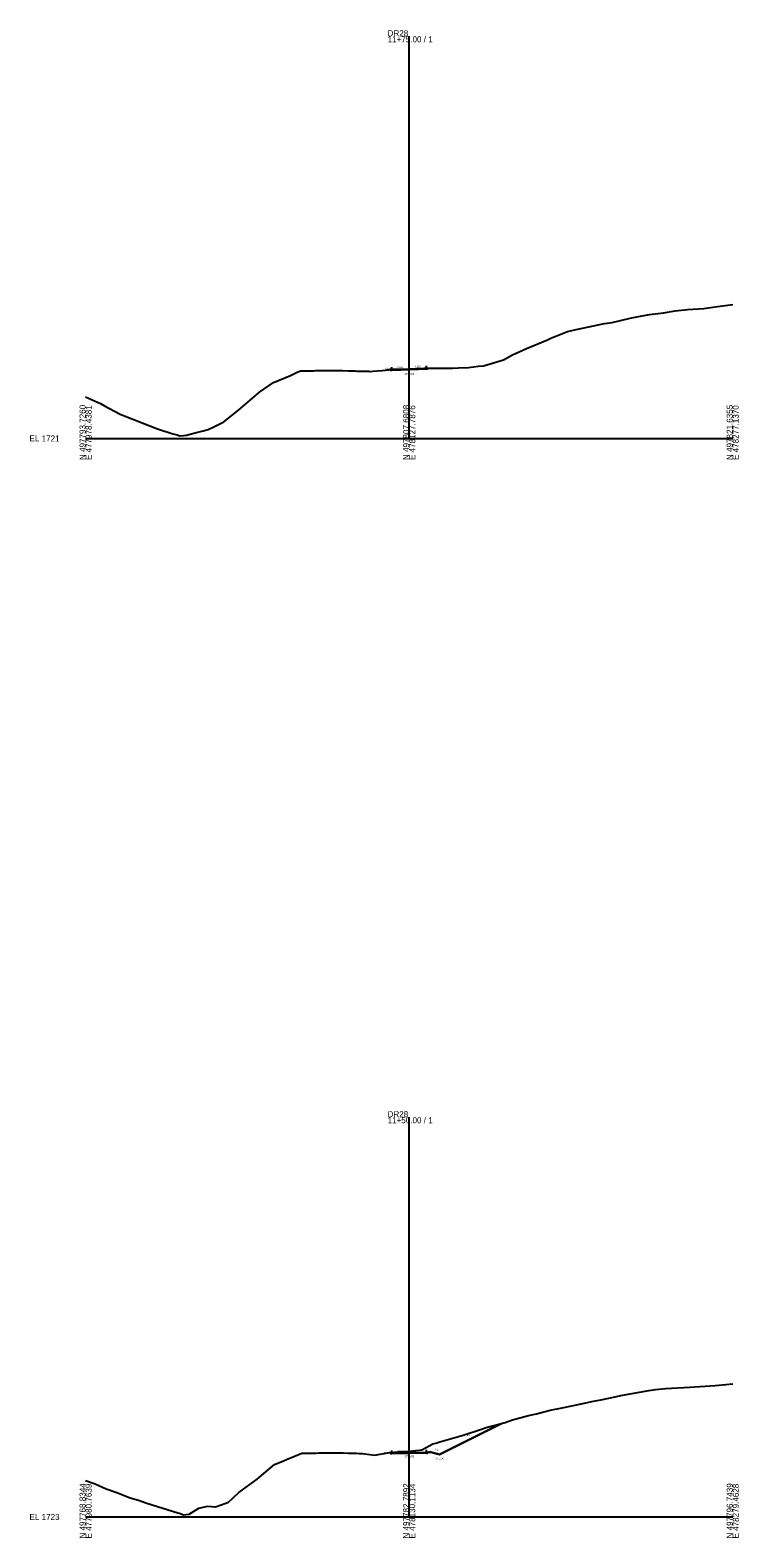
# Model space of a CAD drawing. Extents: x -26 to 303, y -10 to 3689.
# Drawn here: x -26 to 303, y 2990 to 3689 of the extents above; entities that cross this region are included whole.
import ezdxf

# ---------------------------------------------------------------- set-up
doc = ezdxf.new("R2010")
doc.units = 0
for name, color, linetype in [('Exist Cross Section Cell', 7, 'Continuous'), ('Exist XS Center Line Elevation Label', 7, 'Continuous'), ('Exist XS Ground Line', 7, 'Continuous'), ('Prop XS Ditch Slope Text', 7, 'Continuous'), ('Prop XS Ditch Standard Text', 7, 'Continuous'), ('Prop XS Dump Level', 7, 'Continuous'), ('Prop XS Earthwork Shape', 7, 'Continuous'), ('Prop XS EOT Tick Mark', 7, 'Continuous'), ('Prop XS Finish Grade', 7, 'Continuous'), ('Prop XS Finish Grade Earthwork', 7, 'Continuous'), ('Prop XS Finish Grade Pavement', 7, 'Continuous'), ('Prop XS Pvmt Edge Slope', 7, 'Continuous'), ('Prop XS SE Text', 7, 'Continuous'), ('Prop XS Shoulder Borrow Shape', 7, 'Continuous'), ('Prop XS Side Slope Text', 7, 'Continuous'), ('Prop XS Subgrade Earthwork', 7, 'Continuous')]:
    doc.layers.add(name, color=color, linetype=linetype)

msp = doc.modelspace()

# ---------------------------------------------------------------- linework, layer by layer
at = {"layer": 'Exist Cross Section Cell'}
for p, q in [((150, 3500), (150, 3686.46)), ((0, 3500), (150, 3500)), ((150, 3500), (300, 3500)), ((150, 3000), (150, 3185.32)), ((0, 3000), (150, 3000)), ((150, 3000), (300, 3000))]:
    msp.add_line(p, q, dxfattribs=at)
at = {"layer": 'Exist XS Ground Line'}
for points in [[(0, 3519.38), (6.9, 3516.16), (8.83, 3515.14), (16.09, 3511.32), (16.77, 3510.95), (18.41, 3510.29), (33.29, 3504.44), (40.4, 3502.18), (41.27, 3502.01), (42.5, 3501.63), (43.73, 3501.22), (45.35, 3501.36), (46.74, 3501.5), (50.8, 3502.56), (54.58, 3503.54), (56.81, 3504.2), (59.43, 3505.39), (64.05, 3507.76), (70.9, 3513.2), (80.57, 3521.48), (87.19, 3525.97), (94.95, 3529.26), (97.83, 3530.51), (99.67, 3531.32), (101.67, 3531.35), (101.97, 3531.36), (104.13, 3531.39), (105.75, 3531.43), (106.65, 3531.45), (107.71, 3531.47), (109.11, 3531.5), (110.3, 3531.52), (111.64, 3531.56), (112.36, 3531.57), (112.8, 3531.56), (114.17, 3531.52), (116, 3531.5), (116.65, 3531.48), (118.75, 3531.45), (119.13, 3531.44), (121.87, 3531.4), (123.25, 3531.38), (124.18, 3531.37), (124.98, 3531.35), (125.81, 3531.16), (130.17, 3531.18), (131.26, 3531.15), (131.65, 3531.12), (133.24, 3531.22), (137.47, 3531.48), (140.73, 3531.83), (142.26, 3532.06), (144.45, 3532.11), (150, 3532.35), (156.88, 3532.64), (164.99, 3532.59), (170.26, 3532.61), (172.84, 3532.73), (177.5, 3532.89), (182.2, 3533.6), (184.51, 3533.68), (193.8, 3536.41), (197.93, 3538.76), (204.47, 3541.72), (214.13, 3545.8), (215.69, 3546.47), (223.43, 3549.59), (228.8, 3550.86), (230.42, 3551.12), (240.63, 3553.29), (244.05, 3553.78), (252.5, 3555.74), (255.48, 3556.44), (261.37, 3557.51), (267.91, 3558.27), (273.33, 3559.11), (278.98, 3559.78), (286.68, 3560.31), (292.95, 3561.14), (300, 3562.15)], [(0, 3016.83), (4.39, 3015.29), (9.59, 3013.1), (14.43, 3011.26), (20.68, 3008.79), (24.48, 3007.74), (28.32, 3006.32), (42.75, 3001.96), (44.01, 3001.53), (45.29, 3001.04), (46.59, 3001.2), (48.05, 3001.35), (52.43, 3004.07), (56.57, 3005.07), (60.27, 3004.74), (62.91, 3005.67), (66.33, 3006.79), (71.09, 3011.35), (79.47, 3017.51), (87.51, 3024.31), (91.69, 3025.97), (93.2, 3026.6), (96.47, 3027.95), (100.22, 3029.5), (101.35, 3029.52), (101.79, 3029.53), (102.17, 3029.54), (102.65, 3029.54), (104.27, 3029.56), (105.77, 3029.6), (106.8, 3029.63), (108.11, 3029.65), (109.34, 3029.68), (110.79, 3029.72), (111.8, 3029.74), (112.51, 3029.76), (112.87, 3029.77), (113.19, 3029.76), (114.32, 3029.74), (116.33, 3029.7), (116.84, 3029.69), (117.25, 3029.68), (119.35, 3029.65), (121.84, 3029.6), (123.81, 3029.58), (124.44, 3029.57), (125.52, 3029.55), (126.82, 3029.38), (128.33, 3029.35), (133.98, 3028.59), (140.88, 3029.95), (144.95, 3030.24), (147.26, 3030.3), (150, 3030.52), (154.63, 3030.91), (155.87, 3031.18), (161.05, 3033.84), (162.43, 3034.17), (164.21, 3034.78), (175.06, 3037.86), (183.48, 3040.74), (185.7, 3041.52), (194.51, 3043.74), (197.97, 3045.07), (205.3, 3046.99), (209.05, 3047.84), (215.34, 3049.46), (220.13, 3050.39), (225.39, 3051.56), (229.75, 3052.47), (235.43, 3053.64), (238.93, 3054.34), (245.48, 3055.65), (248.12, 3056.33), (261.06, 3058.6), (264.26, 3059.03), (268.91, 3059.49), (280.12, 3060.09), (291.89, 3060.99), (300, 3061.77)]]:
    msp.add_lwpolyline(points, dxfattribs=at)
at = {"layer": 'Prop XS Dump Level'}
for p, q in [((142.01, 3532.06), (150, 3532.35)), ((150, 3532.35), (158, 3532.64)), ((142, 3029.76), (150, 3029.92)), ((150, 3029.92), (158, 3030.08))]:
    msp.add_line(p, q, dxfattribs=at)
at = {"layer": 'Prop XS Earthwork Shape'}
for points in [[(155.87, 3031.18), (161.05, 3033.84), (162.43, 3034.17), (164.21, 3034.78), (175.06, 3037.86), (183.48, 3040.74), (185.7, 3041.52), (192.44, 3043.22), (164, 3029), (160, 3030), (159.02, 3030.04), (158.53, 3029.55), (158, 3029.54), (150, 3029.38), (142, 3029.22), (141.45, 3029.2), (140.98, 3029.68), (138.48, 3029.48), (140.88, 3029.95), (144.95, 3030.24), (147.26, 3030.3), (150, 3030.52), (154.63, 3030.91)], [(162.43, 3034.17), (164.21, 3034.78), (175.06, 3037.86), (183.48, 3040.74), (185.7, 3041.52), (192.44, 3043.22), (164, 3029), (160, 3030), (159.02, 3030.04), (158.53, 3029.55), (158, 3029.54), (150, 3029.38), (142, 3029.22), (141.45, 3029.2), (140.98, 3029.68), (138.48, 3029.48), (140.88, 3029.95), (144.95, 3030.24), (147.26, 3030.3), (150, 3030.52), (154.63, 3030.91), (155.87, 3031.18), (161.05, 3033.84)]]:
    msp.add_lwpolyline(points, close=True, dxfattribs=at)
at = {"layer": 'Prop XS EOT Tick Mark'}
for p, q in [((142.01, 3532.06), (141.99, 3533.06)), ((158, 3532.64), (157.98, 3533.64)), ((142, 3029.76), (142, 3030.76)), ((158, 3030.08), (158, 3031.08))]:
    msp.add_line(p, q, dxfattribs=at)
at = {"layer": 'Prop XS Finish Grade'}
for p, q in [((142.01, 3532.06), (140.98, 3531.96)), ((158, 3532.64), (159.02, 3532.64)), ((142, 3029.76), (140.98, 3029.68)), ((158, 3030.08), (159.02, 3030.04))]:
    msp.add_line(p, q, dxfattribs=at)
at = {"layer": 'Prop XS Finish Grade Earthwork'}
for p, q in [((140.01, 3531.87), (139.27, 3531.67)), ((140.98, 3531.96), (140.01, 3531.87)), ((159.02, 3532.64), (160.12, 3532.62)), ((160.12, 3532.62), (160.12, 3532.62)), ((164, 3029), (192.44, 3043.22)), ((140.98, 3029.68), (138.48, 3029.48)), ((159.02, 3030.04), (160, 3030)), ((160, 3030), (164, 3029))]:
    msp.add_line(p, q, dxfattribs=at)
at = {"layer": 'Prop XS Finish Grade Pavement'}
for p, q in [((142.01, 3532.06), (150, 3532.35)), ((150, 3532.35), (158, 3532.64)), ((142, 3029.76), (150, 3029.92)), ((150, 3029.92), (158, 3030.08))]:
    msp.add_line(p, q, dxfattribs=at)
at = {"layer": 'Prop XS Pvmt Edge Slope'}
for p, q in [((142.01, 3532.06), (141.46, 3531.5)), ((158, 3532.64), (158.54, 3532.11)), ((142, 3029.76), (141.45, 3029.2)), ((158, 3030.08), (158.53, 3029.55))]:
    msp.add_line(p, q, dxfattribs=at)
at = {"layer": 'Prop XS Shoulder Borrow Shape'}
for points in [[(142.01, 3532.06), (140.98, 3531.96), (141.46, 3531.5)], [(158, 3532.64), (159.02, 3532.64), (158.54, 3532.11)], [(142, 3029.76), (140.98, 3029.68), (141.45, 3029.2)], [(158, 3030.08), (159.02, 3030.04), (158.53, 3029.55)]]:
    msp.add_lwpolyline(points, close=True, dxfattribs=at)
at = {"layer": 'Prop XS Subgrade Earthwork'}
for p, q in [((141.46, 3531.5), (140.98, 3531.96)), ((142.01, 3531.52), (141.46, 3531.5)), ((150.01, 3531.81), (142.01, 3531.52)), ((158.54, 3532.11), (150.01, 3531.81)), ((158.54, 3532.11), (159.02, 3532.64)), ((141.45, 3029.2), (140.98, 3029.68)), ((142, 3029.22), (141.45, 3029.2)), ((150, 3029.38), (142, 3029.22)), ((158, 3029.54), (150, 3029.38)), ((158, 3029.54), (158.53, 3029.55)), ((158.53, 3029.55), (159.02, 3030.04))]:
    msp.add_line(p, q, dxfattribs=at)

# ---------------------------------------------------------------- texts
at = {"layer": 'Exist Cross Section Cell'}
for s, p in [('11+75.00 / 1', (140, 3683.66)), ('DR28', (140, 3686.46)), ('EL 1721', (-26, 3498.6)), ('DR28', (140, 3185.32)), ('11+50.00 / 1', (140, 3182.52)), ('EL 1723', (-26, 2998.6))]:
    msp.add_text(s, height=2.8, dxfattribs=at).set_placement(p)
for s, p in [('N 497793.7260', (0, 3490)), ('E 477978.4381', (2.8, 3490)), ('N 497807.6808', (150, 3490)), ('E 478127.7876', (152.8, 3490)), ('N 497821.6355', (300, 3490)), ('E 478277.1370', (302.8, 3490)), ('N 497768.8344', (0, 2990)), ('E 477980.7639', (2.8, 2990)), ('N 497782.7892', (150, 2990)), ('E 478130.1134', (152.8, 2990)), ('N 497796.7439', (300, 2990)), ('E 478279.4628', (302.8, 2990))]:
    msp.add_text(s, height=2.8, rotation=90, dxfattribs=at).set_placement(p)
at = {"layer": 'Exist XS Center Line Elevation Label'}
for s, p in [('1753.35', (147.82, 3529.45)), ('1753.52', (147.83, 3027.62))]:
    msp.add_text(s, height=0.9, dxfattribs=at).set_placement(p)
at = {"layer": 'Prop XS Ditch Slope Text'}
for rotation, p in [(14.95553, (138.81, 3531.93)), (345.96376, (161.85, 3031.08))]:
    msp.add_text('4:1', height=0.75, rotation=rotation, dxfattribs=at).set_placement(p)
at = {"layer": 'Prop XS Ditch Standard Text'}
msp.add_text('1752.00', height=0.75, dxfattribs=at).set_placement((162.23, 3026.75))
at = {"layer": 'Prop XS Dump Level'}
msp.add_text('Case1', height=0.04, rotation=0.91928, dxfattribs=at).set_placement((140.01, 3531.83))
for p in [(140, 3029.56), (160, 3029.96)]:
    msp.add_text('Case1', height=0.04, dxfattribs=at).set_placement(p)
at = {"layer": 'Prop XS SE Text'}
for s, rotation, p in [('0.036', 2.06505, (144.68, 3532.66)), ('0.036', 2.06505, (152.68, 3532.94)), ('0.020', 1.14576, (144.69, 3030.31)), ('0.020', 1.14576, (152.69, 3030.47))]:
    msp.add_text(s, height=0.75, rotation=rotation, dxfattribs=at).set_placement(p)
at = {"layer": 'Prop XS Side Slope Text'}
msp.add_text('2:1', height=0.75, rotation=26.56505, dxfattribs=at).set_placement((177.04, 3037.2))

doc.saveas('drawing.dxf')
